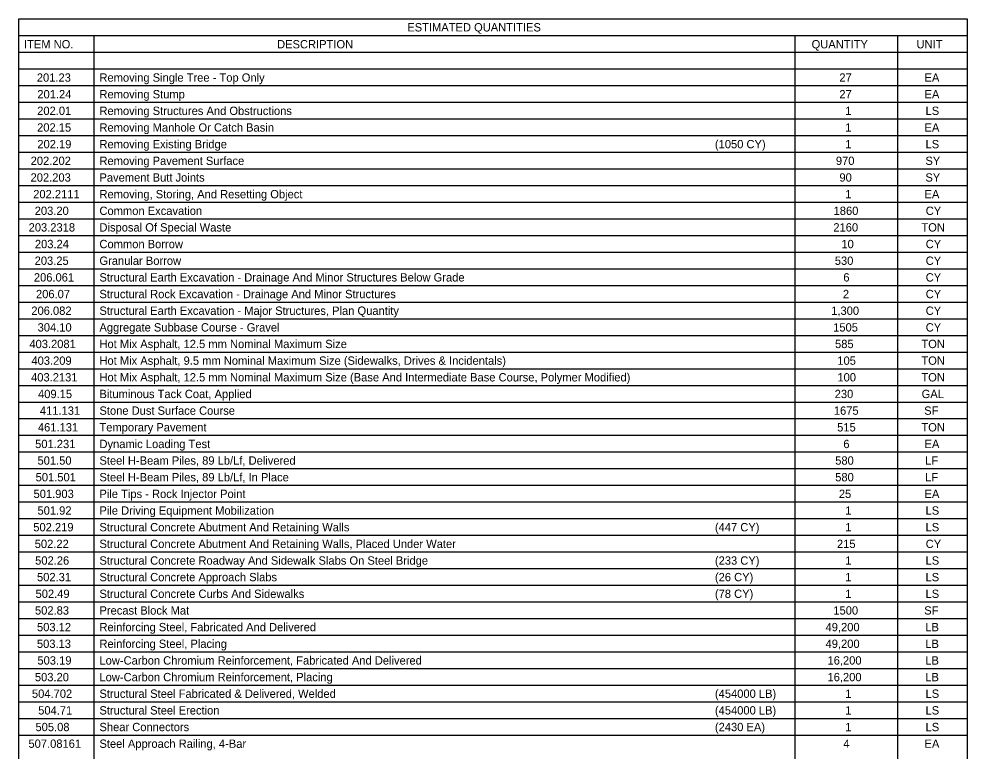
# Model space of a CAD drawing. Extents: x 1005753.14 to 1005755.85, y 326152.24 to 326153.97.
# Drawn here: x 1005753.141 to 1005754.261, y 326153.108 to 326153.974 of the extents above; entities that cross this region are included whole.
import ezdxf

# ---------------------------------------------------------------- set-up
doc = ezdxf.new("R2010")
doc.units = 0
doc.layers.add('ANNOTATION', color=7, linetype='Continuous')
doc.layers.add('BORDER', color=7, linetype='Continuous')

msp = doc.modelspace()

# ---------------------------------------------------------------- linework, layer by layer
at = {"layer": 'BORDER'}
for p, q in [((1005753.1407, 326153.954), (1005754.2614, 326153.954)), ((1005753.2293, 326153.954), (1005753.2293, 326152.2413)), ((1005754.058, 326153.954), (1005754.058, 326152.2413)), ((1005754.1794, 326153.954), (1005754.1794, 326152.2413)), ((1005753.1407, 326153.9343), (1005754.2614, 326153.9343)), ((1005753.1407, 326153.9146), (1005754.2614, 326153.9146)), ((1005753.1407, 326153.8949), (1005754.2614, 326153.8949)), ((1005753.1407, 326153.8753), (1005754.2614, 326153.8753)), ((1005753.1407, 326153.8556), (1005754.2614, 326153.8556)), ((1005753.1407, 326153.8359), (1005754.2614, 326153.8359)), ((1005753.1407, 326153.8162), (1005754.2614, 326153.8162)), ((1005753.1407, 326153.7965), (1005754.2614, 326153.7965)), ((1005753.1407, 326153.7768), (1005754.2614, 326153.7768)), ((1005753.1407, 326153.7571), (1005754.2614, 326153.7571)), ((1005753.1407, 326153.7374), (1005754.2614, 326153.7374)), ((1005753.1407, 326153.7178), (1005754.2614, 326153.7178)), ((1005753.1407, 326153.6981), (1005754.2614, 326153.6981)), ((1005753.1407, 326153.6784), (1005754.2614, 326153.6784)), ((1005753.1407, 326153.6587), (1005754.2614, 326153.6587)), ((1005753.1407, 326153.639), (1005754.2614, 326153.639)), ((1005753.1407, 326153.6193), (1005754.2614, 326153.6193)), ((1005753.1407, 326153.5996), (1005754.2614, 326153.5996)), ((1005753.1407, 326153.58), (1005754.2614, 326153.58)), ((1005753.1407, 326153.5603), (1005754.2614, 326153.5603)), ((1005753.1407, 326153.5406), (1005754.2614, 326153.5406)), ((1005753.1407, 326153.5209), (1005754.2614, 326153.5209)), ((1005753.1407, 326153.5012), (1005754.2614, 326153.5012)), ((1005753.1407, 326153.4815), (1005754.2614, 326153.4815)), ((1005753.1407, 326153.4618), (1005754.2614, 326153.4618)), ((1005753.1407, 326153.4422), (1005754.2614, 326153.4422)), ((1005753.1407, 326153.4225), (1005754.2614, 326153.4225)), ((1005753.1407, 326153.4028), (1005754.2614, 326153.4028)), ((1005753.1407, 326153.3831), (1005754.2614, 326153.3831)), ((1005753.1407, 326153.3634), (1005754.2614, 326153.3634)), ((1005753.1407, 326153.3437), (1005754.2614, 326153.3437)), ((1005753.1407, 326153.324), (1005754.2614, 326153.324)), ((1005753.1407, 326153.3044), (1005754.2614, 326153.3044)), ((1005753.1407, 326153.2847), (1005754.2614, 326153.2847)), ((1005753.1407, 326153.265), (1005754.2614, 326153.265)), ((1005753.1407, 326153.2453), (1005754.2614, 326153.2453)), ((1005753.1407, 326153.2256), (1005754.2614, 326153.2256)), ((1005753.1407, 326153.2059), (1005754.2614, 326153.2059)), ((1005753.1407, 326153.1862), (1005754.2614, 326153.1862)), ((1005753.1407, 326153.1666), (1005754.2614, 326153.1666)), ((1005753.1407, 326153.1469), (1005754.2614, 326153.1469)), ((1005753.1407, 326153.1272), (1005754.2614, 326153.1272))]:
    msp.add_line(p, q, dxfattribs=at)
msp.add_lwpolyline([(1005753.1407, 326153.9737), (1005754.2614, 326153.9737), (1005754.2614, 326152.2413), (1005753.1407, 326152.2413)], close=True, dxfattribs=at)

# ---------------------------------------------------------------- texts
at = {"layer": 'ANNOTATION'}
for s, height, p in [('201.23', 0.00984, (1005753.1618, 326153.8995)), ('Removing Single Tree - Top Only', 0.009843, (1005753.2358, 326153.8995)), ('27', 0.00984, (1005754.1105, 326153.8995)), ('EA', 0.00984, (1005754.2112, 326153.8995)), ('201.24', 0.00984, (1005753.1624, 326153.8798)), ('Removing Stump', 0.009843, (1005753.2358, 326153.8798)), ('27', 0.00984, (1005754.1105, 326153.8798)), ('EA', 0.00984, (1005754.2112, 326153.8798)), ('202.01', 0.00984, (1005753.1622, 326153.8602)), ('Removing Structures And Obstructions', 0.009843, (1005753.2358, 326153.8602)), ('1', 0.00984, (1005754.1175, 326153.8602)), ('LS', 0.00984, (1005754.2124, 326153.8602)), ('202.15', 0.00984, (1005753.1621, 326153.8405)), ('Removing Manhole Or Catch Basin', 0.009843, (1005753.2358, 326153.8405)), ('1', 0.00984, (1005754.1175, 326153.8405)), ('EA', 0.00984, (1005754.2112, 326153.8405)), ('202.19', 0.00984, (1005753.1624, 326153.8208)), ('Removing Existing Bridge', 0.009843, (1005753.2358, 326153.8208)), ('(1050 CY)', 0.00984, (1005753.9634, 326153.8208)), ('1', 0.00984, (1005754.1175, 326153.8208)), ('LS', 0.00984, (1005754.2124, 326153.8208)), ('202.202', 0.00984, (1005753.1545, 326153.8011)), ('Removing Pavement Surface', 0.009843, (1005753.2358, 326153.8011)), ('970', 0.00984, (1005754.1064, 326153.8011)), ('SY', 0.00984, (1005754.2122, 326153.8011)), ('202.203', 0.00984, (1005753.1544, 326153.7814)), ('Pavement Butt Joints', 0.009843, (1005753.2358, 326153.7814)), ('90', 0.00984, (1005754.1106, 326153.7814)), ('SY', 0.00984, (1005754.2122, 326153.7814)), ('202.2111', 0.00984, (1005753.1575, 326153.7617)), ('Removing, Storing, And Resetting Object ', 0.009843, (1005753.2358, 326153.7617)), ('1', 0.00984, (1005754.1175, 326153.7617)), ('EA', 0.00984, (1005754.2112, 326153.7617)), ('203.20', 0.00984, (1005753.1593, 326153.742)), ('Common Excavation', 0.009843, (1005753.2358, 326153.742)), ('1860', 0.00984, (1005754.1037, 326153.742)), ('CY', 0.00984, (1005754.2126, 326153.742)), ('203.2318', 0.00984, (1005753.1521, 326153.7224)), ('Disposal Of Special Waste', 0.009843, (1005753.2358, 326153.7224)), ('2160', 0.00984, (1005754.1034, 326153.7224)), ('TON', 0.00984, (1005754.2075, 326153.7224)), ('203.24', 0.00984, (1005753.1595, 326153.7027)), ('Common Borrow', 0.009843, (1005753.2358, 326153.7027)), ('10', 0.00984, (1005754.1129, 326153.7027)), ('CY', 0.00984, (1005754.2126, 326153.7027)), ('203.25', 0.00984, (1005753.1592, 326153.683)), ('Granular Borrow', 0.009843, (1005753.2358, 326153.683)), ('530', 0.00984, (1005754.1051, 326153.683)), ('CY', 0.00984, (1005754.2126, 326153.683)), ('206.061', 0.00984, (1005753.1583, 326153.6633)), ('Structural Earth Excavation - Drainage And Minor Structures Below Grade', 0.009843, (1005753.2358, 326153.6633)), ('6', 0.00984, (1005754.1152, 326153.6633)), ('CY', 0.00984, (1005754.2126, 326153.6633)), ('206.07', 0.00984, (1005753.1608, 326153.6436)), ('Structural Rock Excavation - Drainage And Minor Structures', 0.009843, (1005753.2358, 326153.6436)), ('2', 0.00984, (1005754.1147, 326153.6436)), ('CY', 0.00984, (1005754.2126, 326153.6436)), ('206.082', 0.00984, (1005753.1553, 326153.6239)), ('Structural Earth Excavation - Major Structures, Plan Quantity', 0.009843, (1005753.2358, 326153.6239)), ('1,300', 0.00984, (1005754.1009, 326153.6239)), ('CY', 0.00984, (1005754.2126, 326153.6239)), ('304.10', 0.00984, (1005753.1627, 326153.6042)), ('Aggregate Subbase Course - Gravel', 0.009843, (1005753.2358, 326153.6042)), ('1505', 0.00984, (1005754.1032, 326153.6042)), ('CY', 0.00984, (1005754.2126, 326153.6042)), ('403.2081', 0.00984, (1005753.153, 326153.5846)), ('Hot Mix Asphalt, 12.5 mm Nominal Maximum Size', 0.009843, (1005753.2358, 326153.5846)), ('585', 0.00984, (1005754.1054, 326153.5846)), ('TON', 0.00984, (1005754.2075, 326153.5846)), ('Hot Mix Asphalt, 9.5 mm Nominal Maximum Size (Sidewalks, Drives & Incidentals)', 0.009843, (1005753.2358, 326153.5649)), ('403.209', 0.00984, (1005753.1554, 326153.5649)), ('105', 0.00984, (1005754.1081, 326153.5649)), ('TON', 0.00984, (1005754.2075, 326153.5649)), ('403.2131', 0.00984, (1005753.155, 326153.5452)), ('Hot Mix Asphalt, 12.5 mm Nominal Maximum Size (Base And Intermediate Base Course, Polymer Modified)', 0.009843, (1005753.2358, 326153.5452)), ('100', 0.00984, (1005754.1082, 326153.5452)), ('TON', 0.00984, (1005754.2075, 326153.5452)), ('409.15', 0.00984, (1005753.1632, 326153.5255)), ('Bituminous Tack Coat, Applied', 0.009843, (1005753.2358, 326153.5255)), ('230', 0.00984, (1005754.105, 326153.5255)), ('GAL', 0.00984, (1005754.2078, 326153.5255)), ('411.131', 0.00984, (1005753.1654, 326153.5058)), ('Stone Dust Surface Course ', 0.009843, (1005753.2358, 326153.5058)), ('1675', 0.00984, (1005754.104, 326153.5058)), ('SF', 0.00984, (1005754.2108, 326153.5058)), ('461.131', 0.00984, (1005753.1631, 326153.4861)), ('Temporary Pavement', 0.009843, (1005753.2358, 326153.4861)), ('515', 0.00984, (1005754.1079, 326153.4861)), ('TON', 0.00984, (1005754.2075, 326153.4861)), ('501.231', 0.00984, (1005753.1598, 326153.4664)), ('Dynamic Loading Test', 0.009843, (1005753.2358, 326153.4664)), ('6', 0.00984, (1005754.1152, 326153.4664)), ('EA', 0.00984, (1005754.2112, 326153.4664)), ('501.50', 0.00984, (1005753.1626, 326153.4468)), ('Steel H-Beam Piles, 89 Lb/Lf, Delivered', 0.009843, (1005753.2358, 326153.4468)), ('580', 0.00984, (1005754.1056, 326153.4468)), ('LF', 0.00984, (1005754.2119, 326153.4468)), ('501.501', 0.00984, (1005753.1604, 326153.4271)), ('Steel H-Beam Piles, 89 Lb/Lf, In Place', 0.009843, (1005753.2358, 326153.4271)), ('580', 0.00984, (1005754.1056, 326153.4271)), ('LF', 0.00984, (1005754.2119, 326153.4271)), ('501.903', 0.00984, (1005753.1579, 326153.4074)), ('Pile Tips - Rock Injector Point', 0.009843, (1005753.2358, 326153.4074)), ('25', 0.00984, (1005754.1099, 326153.4074)), ('EA', 0.00984, (1005754.2112, 326153.4074)), ('501.92', 0.00984, (1005753.1626, 326153.3877)), ('Pile Driving Equipment Mobilization', 0.009843, (1005753.2358, 326153.3877)), ('1', 0.00984, (1005754.1175, 326153.3877)), ('LS', 0.00984, (1005754.2124, 326153.3877)), ('502.219', 0.00984, (1005753.1576, 326153.368)), ('Structural Concrete Abutment And Retaining Walls', 0.009843, (1005753.2358, 326153.368)), ('(447 CY)', 0.00984, (1005753.9634, 326153.368)), ('1', 0.00984, (1005754.1175, 326153.368)), ('LS', 0.00984, (1005754.2124, 326153.368)), ('502.22', 0.00984, (1005753.1593, 326153.3483)), ('Structural Concrete Abutment And Retaining Walls, Placed Under Water', 0.009843, (1005753.2358, 326153.3483)), ('215', 0.00984, (1005754.1077, 326153.3483)), ('CY', 0.00984, (1005754.2126, 326153.3483)), ('502.26', 0.00984, (1005753.1598, 326153.3286)), ('Structural Concrete Roadway And Sidewalk Slabs On Steel Bridge', 0.009843, (1005753.2358, 326153.3286)), ('(233 CY)', 0.00984, (1005753.9634, 326153.3286)), ('1', 0.00984, (1005754.1175, 326153.3286)), ('LS', 0.00984, (1005754.2124, 326153.3286)), ('502.31', 0.00984, (1005753.162, 326153.309)), ('Structural Concrete Approach Slabs', 0.009843, (1005753.2358, 326153.309)), ('(26 CY)', 0.00984, (1005753.9634, 326153.309)), ('1', 0.00984, (1005754.1175, 326153.309)), ('LS', 0.00984, (1005754.2124, 326153.309)), ('502.49', 0.00984, (1005753.1603, 326153.2893)), ('Structural Concrete Curbs And Sidewalks', 0.009843, (1005753.2358, 326153.2893)), ('(78 CY)', 0.00984, (1005753.9634, 326153.2893)), ('1', 0.00984, (1005754.1175, 326153.2893)), ('LS', 0.00984, (1005754.2124, 326153.2893)), ('502.83', 0.00984, (1005753.1596, 326153.2696)), ('Precast Block Mat', 0.009843, (1005753.2358, 326153.2696)), ('1500', 0.00984, (1005754.1034, 326153.2696)), ('SF', 0.00984, (1005754.2108, 326153.2696)), ('503.12', 0.00984, (1005753.162, 326153.2499)), ('Reinforcing Steel, Fabricated And Delivered', 0.009843, (1005753.2358, 326153.2499)), ('49,200', 0.00984, (1005754.0942, 326153.2499)), ('LB', 0.00984, (1005754.2121, 326153.2499)), ('503.13', 0.00984, (1005753.1619, 326153.2302)), ('Reinforcing Steel, Placing', 0.009843, (1005753.2358, 326153.2302)), ('49,200', 0.00984, (1005754.0942, 326153.2302)), ('LB', 0.00984, (1005754.2121, 326153.2302)), ('503.19', 0.00984, (1005753.1625, 326153.2105)), ('Low-Carbon Chromium Reinforcement, Fabricated And Delivered', 0.009843, (1005753.2358, 326153.2105)), ('16,200', 0.00984, (1005754.0965, 326153.2105)), ('LB', 0.00984, (1005754.2121, 326153.2105)), ('503.20', 0.00984, (1005753.1595, 326153.1908)), ('Low-Carbon Chromium Reinforcement, Placing', 0.009843, (1005753.2358, 326153.1908)), ('16,200', 0.00984, (1005754.0965, 326153.1908)), ('LB', 0.00984, (1005754.2121, 326153.1908)), ('504.702', 0.00984, (1005753.156, 326153.1712)), ('Structural Steel Fabricated & Delivered, Welded', 0.009843, (1005753.2358, 326153.1712)), ('(454000 LB)', 0.009843, (1005753.9634, 326153.1712)), ('1', 0.00984, (1005754.1175, 326153.1712)), ('LS', 0.00984, (1005754.2124, 326153.1712)), ('504.71', 0.00984, (1005753.1634, 326153.1515)), ('Structural Steel Erection', 0.009843, (1005753.2358, 326153.1515)), ('(454000 LB)', 0.009843, (1005753.9634, 326153.1515)), ('1', 0.00984, (1005754.1175, 326153.1515)), ('LS', 0.00984, (1005754.2124, 326153.1515)), ('505.08', 0.00984, (1005753.1602, 326153.1318)), ('Shear Connectors', 0.009843, (1005753.2358, 326153.1318)), ('(2430 EA)', 0.00984, (1005753.9634, 326153.1318)), ('1', 0.00984, (1005754.1175, 326153.1318)), ('LS', 0.00984, (1005754.2124, 326153.1318)), ('507.08161', 0.00984, (1005753.1519, 326153.1121)), ('Steel Approach Railing, 4-Bar', 0.009843, (1005753.2358, 326153.1121)), ('4', 0.00984, (1005754.1152, 326153.1121)), ('EA', 0.00984, (1005754.2112, 326153.1121))]:
    msp.add_text(s, height=height, dxfattribs=at).set_placement(p)
at = {"layer": 'BORDER'}
for s, height, p in [('ESTIMATED QUANTITIES', 0.009843, (1005753.5997, 326153.9589)), ('ITEM NO.', 0.00984, (1005753.1466, 326153.9389)), ('DESCRIPTION', 0.009843, (1005753.4458, 326153.9389)), ('QUANTITY', 0.00984, (1005754.0777, 326153.9389)), ('UNIT', 0.00984, (1005754.2017, 326153.9389))]:
    msp.add_text(s, height=height, dxfattribs=at).set_placement(p)

doc.saveas('drawing.dxf')
